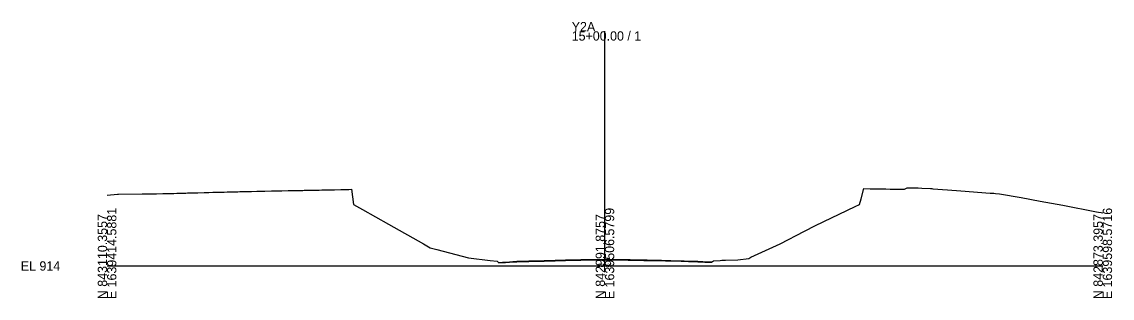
# Model space of a CAD drawing. Extents: x -26 to 303, y -10 to 10517.
# Drawn here: x -25.7 to 302.8, y 4490.3 to 4573.4 of the extents above; entities that cross this region are included whole.
import ezdxf

# ---------------------------------------------------------------- set-up
doc = ezdxf.new("R2010")
doc.units = 0
for name, color, linetype in [('Exist Cross Section Cell', 7, 'Continuous'), ('Exist XS Center Line Elevation Label', 7, 'Continuous'), ('Exist XS Ground Line', 7, 'Continuous'), ('Prop CMT Pvmt Surface Overlay', 7, 'Continuous')]:
    doc.layers.add(name, color=color, linetype=linetype)

msp = doc.modelspace()

# ---------------------------------------------------------------- linework, layer by layer
at = {"layer": 'Exist Cross Section Cell'}
for p, q in [((150, 4500), (150, 4570.6)), ((0, 4500), (150, 4500)), ((150, 4500), (300, 4500))]:
    msp.add_line(p, q, dxfattribs=at)
at = {"layer": 'Exist XS Ground Line'}
msp.add_lwpolyline([(0, 4521.28), (3.09, 4521.59), (3.45, 4521.62), (10.55, 4521.67), (12.4, 4521.67), (13, 4521.67), (14.11, 4521.68), (14.94, 4521.7), (16.8, 4521.76), (17.86, 4521.77), (18.36, 4521.79), (19.02, 4521.8), (20.15, 4521.84), (21.02, 4521.86), (21.93, 4521.89), (23.09, 4521.92), (23.71, 4521.94), (24.19, 4521.96), (25.49, 4521.99), (27.35, 4522.04), (29.22, 4522.09), (30.31, 4522.12), (30.63, 4522.13), (31.91, 4522.16), (33.68, 4522.2), (34.4, 4522.22), (35.32, 4522.24), (36.18, 4522.27), (36.85, 4522.28), (37.96, 4522.3), (39.4, 4522.34), (40.01, 4522.36), (41.53, 4522.39), (43.47, 4522.44), (45.09, 4522.48), (46.34, 4522.5), (47.55, 4522.53), (49.51, 4522.57), (50.43, 4522.59), (51.63, 4522.61), (52.22, 4522.62), (52.67, 4522.63), (54.54, 4522.66), (55.84, 4522.68), (56.27, 4522.69), (57.01, 4522.71), (59, 4522.74), (59.34, 4522.76), (59.78, 4522.77), (60.41, 4522.78), (62.17, 4522.81), (62.91, 4522.82), (63.86, 4522.84), (64.69, 4522.86), (65.33, 4522.88), (66.47, 4522.91), (67.93, 4522.93), (68.5, 4522.94), (70.47, 4522.99), (71.92, 4523.03), (72.81, 4523.05), (73.66, 4523.07), (74.27, 4518.47), (76.93, 4516.98), (84.8, 4512.58), (95.33, 4506.62), (97.39, 4505.46), (99.32, 4504.95), (108.92, 4502.41), (115.47, 4501.66), (117.57, 4501.43), (118.01, 4500.95), (119.15, 4501), (120.01, 4501.03), (121.23, 4501.15), (122.31, 4501.23), (123.49, 4501.27), (125.47, 4501.32), (127.1, 4501.36), (129.08, 4501.41), (131.67, 4501.48), (132.11, 4501.49), (133.16, 4501.52), (134.18, 4501.54), (134.97, 4501.57), (137.23, 4501.64), (138.13, 4501.66), (141.31, 4501.73), (142.72, 4501.76), (143.95, 4501.79), (144.46, 4501.8), (144.87, 4501.81), (145.39, 4501.82), (146.75, 4501.83), (147.43, 4501.85), (149.46, 4501.86), (150.21, 4501.86), (150.79, 4501.85), (153.54, 4501.82), (153.96, 4501.82), (155.6, 4501.79), (157, 4501.77), (157.61, 4501.77), (160.29, 4501.71), (161.69, 4501.68), (162.68, 4501.67), (163.45, 4501.65), (164.46, 4501.63), (165.77, 4501.61), (166.25, 4501.6), (166.62, 4501.6), (167.01, 4501.59), (168.3, 4501.56), (169.84, 4501.52), (172.95, 4501.43), (173.92, 4501.4), (175.15, 4501.35), (176.11, 4501.33), (178, 4501.28), (179.44, 4501.21), (180.09, 4501.16), (181.35, 4501.12), (182.07, 4501.09), (182.67, 4501.55), (184.71, 4501.66), (185.18, 4501.69), (185.81, 4501.73), (186.28, 4501.74), (190, 4501.83), (193.31, 4502.29), (193.99, 4502.6), (202.82, 4506.66), (210.16, 4510.48), (213.45, 4512.2), (225.37, 4517.85), (226.71, 4518.49), (227.18, 4520.24), (227.96, 4523.27), (229.92, 4523.23), (230.31, 4523.21), (230.99, 4523.22), (232.17, 4523.21), (233.08, 4523.2), (234.28, 4523.17), (234.59, 4523.16), (235.97, 4523.15), (236.51, 4523.14), (237.58, 4523.13), (238.76, 4523.11), (240.26, 4523.12), (241.06, 4523.53), (242.96, 4523.5), (243.52, 4523.5), (244.04, 4523.5), (244.37, 4523.47), (245.45, 4523.43), (248.11, 4523.32), (248.46, 4523.28), (248.83, 4523.25), (253.18, 4522.89), (257.26, 4522.56), (266.04, 4521.93), (267.13, 4521.86), (267.64, 4521.82), (268.88, 4521.73), (275.46, 4520.6), (281.11, 4519.52), (288.01, 4518.27), (298.14, 4516.28), (298.72, 4516.18), (299.48, 4516.05), (300, 4515.97)], dxfattribs=at)
at = {"layer": 'Prop CMT Pvmt Surface Overlay'}
msp.add_lwpolyline([(117.9, 4501.07), (119.15, 4501.12), (120, 4501.16), (121.22, 4501.28), (122.3, 4501.35), (123.48, 4501.39), (125.47, 4501.45), (127.09, 4501.49), (129.08, 4501.54), (131.67, 4501.6), (132.11, 4501.61), (133.15, 4501.64), (134.17, 4501.67), (134.96, 4501.69), (137.23, 4501.77), (138.13, 4501.79), (141.31, 4501.85), (142.72, 4501.89), (143.95, 4501.91), (144.46, 4501.92), (144.86, 4501.93), (145.38, 4501.94), (146.75, 4501.96), (147.43, 4501.97), (149.46, 4501.98), (150.21, 4501.98), (150.79, 4501.97), (153.54, 4501.94), (153.96, 4501.94), (155.6, 4501.92), (157, 4501.9), (157.62, 4501.89), (160.29, 4501.83), (161.69, 4501.81), (162.69, 4501.79), (163.46, 4501.78), (164.47, 4501.75), (165.77, 4501.73), (166.25, 4501.73), (166.62, 4501.72), (167.01, 4501.71), (168.3, 4501.68), (169.85, 4501.65), (172.95, 4501.55), (173.92, 4501.52), (175.16, 4501.48), (176.12, 4501.45), (178, 4501.4), (179.45, 4501.33), (180.1, 4501.28), (181.35, 4501.24), (182.23, 4501.21)], dxfattribs=at)

# ---------------------------------------------------------------- texts
at = {"layer": 'Exist Cross Section Cell'}
for s, p in [('Y2A', (140, 4570.6)), ('15+00.00 / 1', (140, 4567.8)), ('EL 914', (-26, 4498.6))]:
    msp.add_text(s, height=2.8, dxfattribs=at).set_placement(p)
for s, p in [('N 843110.3557', (0, 4490)), ('E 1639414.5881', (2.8, 4490)), ('N 842991.8757', (150, 4490)), ('E 1639506.5799', (152.8, 4490)), ('N 842873.3957', (300, 4490)), ('E 1639598.5716', (302.8, 4490))]:
    msp.add_text(s, height=2.8, rotation=90, dxfattribs=at).set_placement(p)
at = {"layer": 'Exist XS Center Line Elevation Label'}
msp.add_text('915.86', height=1, dxfattribs=at).set_placement((147.94, 4499.69))

doc.saveas('drawing.dxf')
